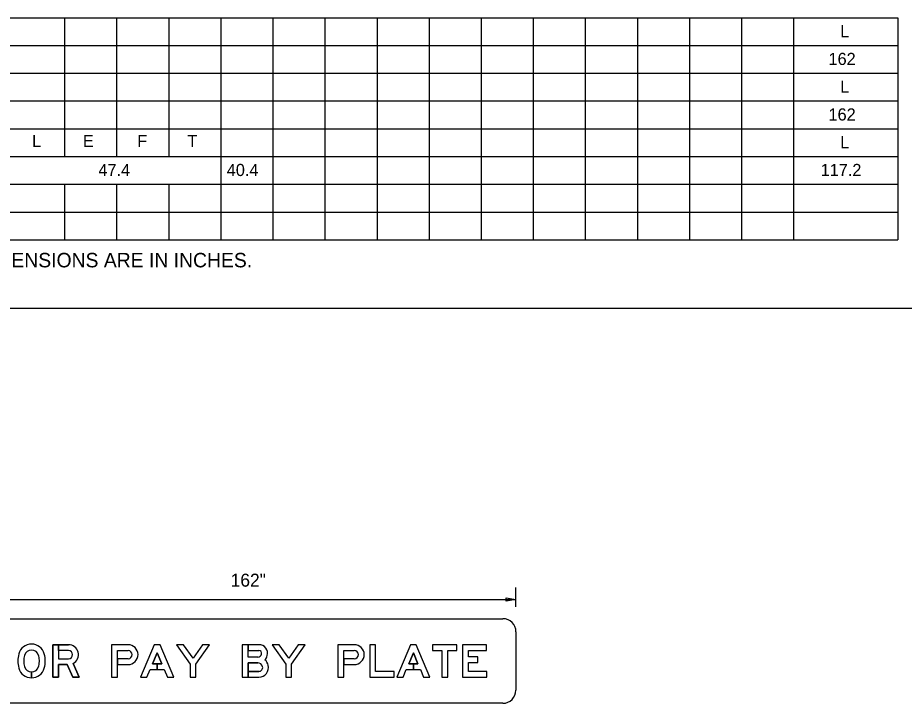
# Model space of a CAD drawing. Extents: x 10268312 to 10268706, y 2142548 to 2142786.
# Drawn here: x 10268343.3 to 10268394.4, y 2142617.5 to 2142657 of the extents above; entities that cross this region are included whole.
import ezdxf

# ---------------------------------------------------------------- set-up
doc = ezdxf.new("R2010")
doc.units = 0
for name, color, linetype in [('GSBWFill', 7, 'Continuous'), ('GSDims', 7, 'Continuous'), ('SheetBorder_dp', 7, 'Continuous'), ('SignPanel', 7, 'Continuous'), ('SumBoxLines_dp', 7, 'Continuous'), ('SumBoxLinesMin_dp', 7, 'Continuous'), ('TextLabel', 7, 'Continuous'), ('TextNotes', 7, 'Continuous')]:
    doc.layers.add(name, color=color, linetype=linetype)

msp = doc.modelspace()

# ---------------------------------------------------------------- linework, layer by layer
at = {"layer": 'GSBWFill'}
for p, q in [((10268342.368, 2142622.39), (10268371.236, 2142622.39)), ((10268371.986, 2142621.64), (10268371.986, 2142618.265)), ((10268371.236, 2142617.515), (10268342.368, 2142617.515))]:
    msp.add_line(p, q, dxfattribs=at)
for centre, start, end in [((10268371.236, 2142621.64), 0, 90), ((10268371.229, 2142618.265), 270, 0)]:
    msp.add_arc(centre, 0.75, start, end, dxfattribs=at)
at = {"layer": 'GSDims'}
for p, q in [((10268371.986, 2142623.07), (10268371.986, 2142624.195)), ((10268341.618, 2142623.492), (10268371.986, 2142623.492))]:
    msp.add_line(p, q, dxfattribs=at)
msp.add_lwpolyline([(10268371.986, 2142623.492), (10268371.424, 2142623.398), (10268371.424, 2142623.586)], close=True, dxfattribs=at)
at = {"layer": 'SheetBorder_dp'}
msp.add_line((10268317.73, 2142640.282), (10268471.73, 2142640.282), dxfattribs=at)
at = {"layer": 'SignPanel'}
for p, q in [((10268349.03, 2142620.552), (10268349.64, 2142620.552)), ((10268349.03, 2142620.552), (10268349.64, 2142620.552)), ((10268349.03, 2142620.552), (10268349.64, 2142620.552)), ((10268362.062, 2142620.552), (10268362.671, 2142620.552)), ((10268362.062, 2142620.552), (10268362.671, 2142620.552)), ((10268362.062, 2142620.552), (10268362.671, 2142620.552)), ((10268344.08, 2142618.982), (10268344.08, 2142619.319)), ((10268344.08, 2142619.319), (10268344.08, 2142618.982)), ((10268344.08, 2142618.982), (10268344.08, 2142619.319)), ((10268344.08, 2142619.319), (10268344.08, 2142618.982)), ((10268349.03, 2142619.746), (10268349.64, 2142619.746)), ((10268362.062, 2142619.746), (10268362.671, 2142619.746)), ((10268356.212, 2142619.015), (10268357.177, 2142619.015))]:
    msp.add_line(p, q, dxfattribs=at)
for points in [[(10268346.206, 2142620.89), (10268345.299, 2142620.89), (10268345.299, 2142619.015), (10268345.637, 2142619.015), (10268345.637, 2142619.746), (10268346.133, 2142619.746), (10268346.45, 2142619.015), (10268346.818, 2142619.015), (10268346.473, 2142619.812)], [(10268346.473, 2142619.812), (10268346.818, 2142619.015), (10268346.45, 2142619.015), (10268346.133, 2142619.746), (10268345.637, 2142619.746), (10268345.637, 2142619.015), (10268345.299, 2142619.015), (10268345.299, 2142620.89), (10268345.637, 2142620.89), (10268345.637, 2142620.083), (10268346.206, 2142620.083)], [(10268346.473, 2142619.812), (10268346.818, 2142619.015), (10268346.45, 2142619.015), (10268346.133, 2142619.746), (10268345.637, 2142619.746), (10268345.637, 2142619.015), (10268345.299, 2142619.015), (10268345.299, 2142620.89), (10268345.637, 2142620.89), (10268345.637, 2142620.083), (10268346.206, 2142620.083)], [(10268345.637, 2142620.552), (10268345.637, 2142620.89), (10268346.206, 2142620.89)], [(10268345.637, 2142620.552), (10268345.637, 2142620.89), (10268346.206, 2142620.89)], [(10268349.64, 2142620.89), (10268348.693, 2142620.89), (10268348.693, 2142619.015), (10268349.03, 2142619.015), (10268349.03, 2142619.746)], [(10268349.64, 2142620.89), (10268348.693, 2142620.89), (10268348.693, 2142619.015), (10268349.03, 2142619.015), (10268349.03, 2142620.552)], [(10268349.64, 2142620.89), (10268348.693, 2142620.89), (10268348.693, 2142619.015), (10268349.03, 2142619.015), (10268349.03, 2142620.552)], [(10268357.177, 2142620.89), (10268356.212, 2142620.89), (10268356.212, 2142619.015)], [(10268357.105, 2142620.177), (10268356.549, 2142620.177), (10268356.549, 2142620.89), (10268356.212, 2142620.89), (10268356.212, 2142619.015), (10268356.549, 2142619.015)], [(10268357.105, 2142620.177), (10268356.549, 2142620.177), (10268356.549, 2142620.89), (10268356.212, 2142620.89), (10268356.212, 2142619.015), (10268356.549, 2142619.015)], [(10268357.177, 2142620.89), (10268356.549, 2142620.89), (10268356.549, 2142620.552), (10268357.177, 2142620.552)], [(10268357.177, 2142620.89), (10268356.549, 2142620.89), (10268356.549, 2142620.552), (10268357.177, 2142620.552)], [(10268362.671, 2142620.89), (10268361.724, 2142620.89), (10268361.724, 2142619.015), (10268362.062, 2142619.015), (10268362.062, 2142619.746)], [(10268362.671, 2142620.89), (10268361.724, 2142620.89), (10268361.724, 2142619.015), (10268362.062, 2142619.015), (10268362.062, 2142620.552)], [(10268362.671, 2142620.89), (10268361.724, 2142620.89), (10268361.724, 2142619.015), (10268362.062, 2142619.015), (10268362.062, 2142620.552)], [(10268346.206, 2142620.552), (10268345.637, 2142620.552), (10268345.637, 2142620.083), (10268346.206, 2142620.083)], [(10268346.206, 2142620.552), (10268345.637, 2142620.552)], [(10268346.206, 2142620.552), (10268345.637, 2142620.552)], [(10268349.64, 2142620.083), (10268349.03, 2142620.083), (10268349.03, 2142620.552)], [(10268357.105, 2142620.177), (10268356.549, 2142620.177), (10268356.549, 2142620.552), (10268357.177, 2142620.552)], [(10268362.671, 2142620.083), (10268362.062, 2142620.083), (10268362.062, 2142620.552)], [(10268349.64, 2142620.083), (10268349.03, 2142620.083), (10268349.03, 2142619.746), (10268349.64, 2142619.746)], [(10268349.64, 2142620.083), (10268349.03, 2142620.083), (10268349.03, 2142619.746), (10268349.64, 2142619.746)], [(10268357.105, 2142619.84), (10268356.549, 2142619.84), (10268356.549, 2142619.352), (10268357.177, 2142619.352)], [(10268356.549, 2142619.015), (10268356.549, 2142619.84), (10268357.105, 2142619.84)], [(10268356.549, 2142619.015), (10268356.549, 2142619.84), (10268357.105, 2142619.84)], [(10268362.671, 2142620.083), (10268362.062, 2142620.083), (10268362.062, 2142619.746), (10268362.671, 2142619.746)], [(10268362.671, 2142620.083), (10268362.062, 2142620.083), (10268362.062, 2142619.746), (10268362.671, 2142619.746)], [(10268357.177, 2142619.352), (10268356.549, 2142619.352), (10268356.549, 2142619.015), (10268357.177, 2142619.015)], [(10268357.177, 2142619.352), (10268356.549, 2142619.352), (10268356.549, 2142619.015), (10268357.177, 2142619.015)]]:
    msp.add_lwpolyline(points, dxfattribs=at)
for points in [[(10268350.913, 2142619.455), (10268351.723, 2142619.455), (10268351.908, 2142619.015), (10268352.274, 2142619.015), (10268351.487, 2142620.89), (10268351.149, 2142620.89), (10268350.362, 2142619.015), (10268350.728, 2142619.015)], [(10268351.581, 2142619.793), (10268351.318, 2142619.793), (10268351.318, 2142619.455), (10268351.723, 2142619.455), (10268351.908, 2142619.015), (10268352.274, 2142619.015), (10268351.487, 2142620.89), (10268351.149, 2142620.89), (10268350.362, 2142619.015), (10268350.728, 2142619.015), (10268350.913, 2142619.455), (10268351.318, 2142619.455), (10268351.318, 2142619.793), (10268351.054, 2142619.793), (10268351.318, 2142620.42)], [(10268351.581, 2142619.793), (10268351.318, 2142619.793), (10268351.318, 2142619.455), (10268351.723, 2142619.455), (10268351.908, 2142619.015), (10268352.274, 2142619.015), (10268351.487, 2142620.89), (10268351.149, 2142620.89), (10268350.362, 2142619.015), (10268350.728, 2142619.015), (10268350.913, 2142619.455), (10268351.318, 2142619.455), (10268351.318, 2142619.793), (10268351.054, 2142619.793), (10268351.318, 2142620.42)], [(10268353.549, 2142619.774), (10268354.337, 2142620.89), (10268353.923, 2142620.89), (10268353.38, 2142620.12), (10268352.837, 2142620.89), (10268352.424, 2142620.89), (10268353.212, 2142619.774), (10268353.212, 2142619.015), (10268353.549, 2142619.015)], [(10268353.549, 2142619.774), (10268354.337, 2142620.89), (10268353.923, 2142620.89), (10268353.38, 2142620.12), (10268352.837, 2142620.89), (10268352.424, 2142620.89), (10268353.212, 2142619.774), (10268353.212, 2142619.015), (10268353.549, 2142619.015)], [(10268353.549, 2142619.774), (10268354.337, 2142620.89), (10268353.923, 2142620.89), (10268353.38, 2142620.12), (10268352.837, 2142620.89), (10268352.424, 2142620.89), (10268353.212, 2142619.774), (10268353.212, 2142619.015), (10268353.549, 2142619.015)], [(10268359.062, 2142619.774), (10268359.849, 2142620.89), (10268359.436, 2142620.89), (10268358.893, 2142620.12), (10268358.35, 2142620.89), (10268357.937, 2142620.89), (10268358.724, 2142619.774), (10268358.724, 2142619.015), (10268359.062, 2142619.015)], [(10268359.062, 2142619.774), (10268359.849, 2142620.89), (10268359.436, 2142620.89), (10268358.893, 2142620.12), (10268358.35, 2142620.89), (10268357.937, 2142620.89), (10268358.724, 2142619.774), (10268358.724, 2142619.015), (10268359.062, 2142619.015)], [(10268359.062, 2142619.774), (10268359.849, 2142620.89), (10268359.436, 2142620.89), (10268358.893, 2142620.12), (10268358.35, 2142620.89), (10268357.937, 2142620.89), (10268358.724, 2142619.774), (10268358.724, 2142619.015), (10268359.062, 2142619.015)], [(10268364.968, 2142619.015), (10268364.968, 2142619.343), (10268363.899, 2142619.343), (10268363.899, 2142620.89), (10268363.562, 2142620.89), (10268363.562, 2142619.015)], [(10268364.968, 2142619.015), (10268364.968, 2142619.343), (10268363.899, 2142619.343), (10268363.899, 2142620.89), (10268363.562, 2142620.89), (10268363.562, 2142619.015)], [(10268364.968, 2142619.015), (10268364.968, 2142619.343), (10268363.899, 2142619.343), (10268363.899, 2142620.89), (10268363.562, 2142620.89), (10268363.562, 2142619.015)], [(10268365.669, 2142619.455), (10268366.479, 2142619.455), (10268366.664, 2142619.015), (10268367.03, 2142619.015), (10268366.243, 2142620.89), (10268365.905, 2142620.89), (10268365.118, 2142619.015), (10268365.484, 2142619.015)], [(10268366.338, 2142619.793), (10268366.074, 2142619.793), (10268366.074, 2142619.455), (10268366.479, 2142619.455), (10268366.664, 2142619.015), (10268367.03, 2142619.015), (10268366.243, 2142620.89), (10268365.905, 2142620.89), (10268365.118, 2142619.015), (10268365.484, 2142619.015), (10268365.669, 2142619.455), (10268366.074, 2142619.455), (10268366.074, 2142619.793), (10268365.811, 2142619.793), (10268366.074, 2142620.42)], [(10268366.338, 2142619.793), (10268366.074, 2142619.793), (10268366.074, 2142619.455), (10268366.479, 2142619.455), (10268366.664, 2142619.015), (10268367.03, 2142619.015), (10268366.243, 2142620.89), (10268365.905, 2142620.89), (10268365.118, 2142619.015), (10268365.484, 2142619.015), (10268365.669, 2142619.455), (10268366.074, 2142619.455), (10268366.074, 2142619.793), (10268365.811, 2142619.793), (10268366.074, 2142620.42)], [(10268367.18, 2142620.552), (10268367.715, 2142620.552), (10268367.715, 2142619.015), (10268368.052, 2142619.015), (10268368.052, 2142620.552), (10268368.587, 2142620.552), (10268368.587, 2142620.89), (10268367.18, 2142620.89)], [(10268367.18, 2142620.552), (10268367.715, 2142620.552), (10268367.715, 2142619.015), (10268368.052, 2142619.015), (10268368.052, 2142620.552), (10268368.587, 2142620.552), (10268368.587, 2142620.89), (10268367.18, 2142620.89)], [(10268367.18, 2142620.552), (10268367.715, 2142620.552), (10268367.715, 2142619.015), (10268368.052, 2142619.015), (10268368.052, 2142620.552), (10268368.587, 2142620.552), (10268368.587, 2142620.89), (10268367.18, 2142620.89)], [(10268370.312, 2142619.352), (10268369.243, 2142619.352), (10268369.243, 2142619.856), (10268369.796, 2142619.856), (10268369.796, 2142620.194), (10268369.243, 2142620.194), (10268369.243, 2142620.552), (10268370.284, 2142620.552), (10268370.284, 2142620.89), (10268368.905, 2142620.89), (10268368.905, 2142619.015), (10268370.312, 2142619.015)], [(10268370.312, 2142619.352), (10268369.243, 2142619.352), (10268369.243, 2142619.856), (10268369.796, 2142619.856), (10268369.796, 2142620.194), (10268369.243, 2142620.194), (10268369.243, 2142620.552), (10268370.284, 2142620.552), (10268370.284, 2142620.89), (10268368.905, 2142620.89), (10268368.905, 2142619.015), (10268370.312, 2142619.015)], [(10268370.312, 2142619.352), (10268369.243, 2142619.352), (10268369.243, 2142619.856), (10268369.796, 2142619.856), (10268369.796, 2142620.194), (10268369.243, 2142620.194), (10268369.243, 2142620.552), (10268370.284, 2142620.552), (10268370.284, 2142620.89), (10268368.905, 2142620.89), (10268368.905, 2142619.015), (10268370.312, 2142619.015)], [(10268351.581, 2142619.793), (10268351.318, 2142620.42), (10268351.054, 2142619.793)], [(10268366.338, 2142619.793), (10268366.074, 2142620.42), (10268365.811, 2142619.793)]]:
    msp.add_lwpolyline(points, close=True, dxfattribs=at)
for centre, radius, start, end in [((10268344.08, 2142620.163), 0.76, 14.9618, 165.0382), ((10268344.08, 2142620.163), 0.76, 14.9618, 165.0382), ((10268344.08, 2142620.163), 0.76, 14.9618, 165.0382), ((10268346.206, 2142620.318), 0.572, 297.837, 90), ((10268346.206, 2142620.318), 0.572, 297.837, 90), ((10268346.206, 2142620.318), 0.572, 297.837, 90), ((10268349.64, 2142620.318), 0.572, 270, 90), ((10268349.64, 2142620.318), 0.572, 270, 90), ((10268349.64, 2142620.318), 0.572, 270, 90), ((10268357.177, 2142620.393), 0.497, 345.5225, 90), ((10268357.177, 2142620.393), 0.497, 345.5225, 90), ((10268357.177, 2142620.393), 0.497, 345.5225, 90), ((10268362.671, 2142620.318), 0.572, 270, 90), ((10268362.671, 2142620.318), 0.572, 270, 90), ((10268362.671, 2142620.318), 0.572, 270, 90), ((10268344.868, 2142619.952), 1.575, 165.0382, 194.9618), ((10268344.868, 2142619.952), 1.575, 165.0382, 194.9618), ((10268344.868, 2142619.952), 1.575, 165.0382, 194.9618), ((10268344.08, 2142620.163), 0.422, 14.9618, 165.0382), ((10268344.08, 2142620.163), 0.422, 14.9618, 165.0382), ((10268344.08, 2142620.163), 0.422, 14.9618, 165.0382), ((10268343.293, 2142619.952), 1.575, 345.0382, 14.9618), ((10268343.293, 2142619.952), 1.575, 345.0382, 14.9618), ((10268343.293, 2142619.952), 1.575, 345.0382, 14.9618), ((10268346.206, 2142620.318), 0.234, 270, 90), ((10268346.206, 2142620.318), 0.234, 270, 90), ((10268346.206, 2142620.318), 0.234, 270, 90), ((10268349.64, 2142620.318), 0.234, 270, 90), ((10268349.64, 2142620.318), 0.234, 270, 90), ((10268349.64, 2142620.318), 0.234, 270, 90), ((10268357.105, 2142620.412), 0.234, 270, 345.5225), ((10268357.105, 2142620.412), 0.234, 270, 345.5225), ((10268357.105, 2142620.412), 0.234, 270, 345.5225), ((10268357.177, 2142620.393), 0.159, 345.5225, 90), ((10268357.177, 2142620.393), 0.159, 345.5225, 90), ((10268357.177, 2142620.393), 0.159, 345.5225, 90), ((10268362.671, 2142620.318), 0.234, 270, 90), ((10268362.671, 2142620.318), 0.234, 270, 90), ((10268362.671, 2142620.318), 0.234, 270, 90), ((10268344.868, 2142619.952), 1.238, 165.0382, 194.9618), ((10268344.868, 2142619.952), 1.238, 165.0382, 194.9618), ((10268344.868, 2142619.952), 1.238, 165.0382, 194.9618), ((10268343.293, 2142619.952), 1.238, 345.0382, 14.9618), ((10268343.293, 2142619.952), 1.238, 345.0382, 14.9618), ((10268343.293, 2142619.952), 1.238, 345.0382, 14.9618), ((10268357.105, 2142619.549), 0.291, 14.4775, 90), ((10268357.105, 2142619.549), 0.291, 14.4775, 90), ((10268357.105, 2142619.549), 0.291, 14.4775, 90), ((10268357.105, 2142620.412), 0.572, 316.7114, 345.5225), ((10268357.105, 2142620.412), 0.572, 316.7114, 345.5225), ((10268357.105, 2142620.412), 0.572, 316.7114, 345.5225), ((10268357.105, 2142619.549), 0.628, 14.4775, 48.4921), ((10268357.105, 2142619.549), 0.628, 14.4775, 48.4921), ((10268357.105, 2142619.549), 0.628, 14.4775, 48.4921), ((10268344.08, 2142619.742), 0.76, 194.9618, 345.0382), ((10268344.08, 2142619.742), 0.76, 194.9618, 270), ((10268344.08, 2142619.742), 0.76, 194.9618, 270), ((10268344.08, 2142619.742), 0.422, 194.9618, 345.0382), ((10268344.08, 2142619.742), 0.422, 194.9618, 270), ((10268344.08, 2142619.742), 0.422, 194.9618, 270), ((10268344.08, 2142619.742), 0.422, 270.0127, 345.0382), ((10268344.08, 2142619.742), 0.422, 270.0127, 345.0382), ((10268344.08, 2142619.742), 0.76, 270.0071, 345.0382), ((10268344.08, 2142619.742), 0.76, 270.0071, 345.0382), ((10268357.177, 2142619.568), 0.553, 270, 14.4775), ((10268357.177, 2142619.568), 0.553, 270, 14.4775), ((10268357.177, 2142619.568), 0.553, 270, 14.4775), ((10268357.177, 2142619.568), 0.216, 270, 14.4775), ((10268357.177, 2142619.568), 0.216, 270, 14.4775), ((10268357.177, 2142619.568), 0.216, 270, 14.4775)]:
    msp.add_arc(centre, radius, start, end, dxfattribs=at)
at = {"layer": 'SumBoxLines_dp'}
for p, q in [((10268318.48, 2142657.032), (10268393.98, 2142657.032)), ((10268345.98, 2142657.032), (10268345.98, 2142653.832)), ((10268348.98, 2142657.032), (10268348.98, 2142653.832)), ((10268351.98, 2142657.032), (10268351.98, 2142653.832)), ((10268354.98, 2142657.032), (10268354.98, 2142653.832)), ((10268357.98, 2142657.032), (10268357.98, 2142655.432)), ((10268360.98, 2142657.032), (10268360.98, 2142655.432)), ((10268363.98, 2142657.032), (10268363.98, 2142653.832)), ((10268366.98, 2142657.032), (10268366.98, 2142653.832)), ((10268369.98, 2142657.032), (10268369.98, 2142655.432)), ((10268372.98, 2142657.032), (10268372.98, 2142655.432)), ((10268375.98, 2142657.032), (10268375.98, 2142655.432)), ((10268378.98, 2142657.032), (10268378.98, 2142655.432)), ((10268381.98, 2142657.032), (10268381.98, 2142655.432)), ((10268384.98, 2142657.032), (10268384.98, 2142655.432)), ((10268387.98, 2142657.032), (10268387.98, 2142655.432)), ((10268393.98, 2142657.032), (10268393.98, 2142644.232)), ((10268357.98, 2142655.432), (10268357.98, 2142649.032)), ((10268360.98, 2142655.432), (10268360.98, 2142647.432)), ((10268363.98, 2142655.432), (10268363.98, 2142647.432)), ((10268366.98, 2142655.432), (10268366.98, 2142649.032)), ((10268369.98, 2142655.432), (10268369.98, 2142649.032)), ((10268372.98, 2142655.432), (10268372.98, 2142644.232)), ((10268375.98, 2142655.432), (10268375.98, 2142644.232)), ((10268378.98, 2142655.432), (10268378.98, 2142649.032)), ((10268381.98, 2142655.432), (10268381.98, 2142649.032)), ((10268384.98, 2142655.432), (10268384.98, 2142649.032)), ((10268387.98, 2142655.432), (10268387.98, 2142644.232)), ((10268318.48, 2142653.832), (10268393.98, 2142653.832)), ((10268345.98, 2142653.832), (10268345.98, 2142650.632)), ((10268348.98, 2142653.832), (10268348.98, 2142650.632)), ((10268351.98, 2142653.832), (10268351.98, 2142650.632)), ((10268354.98, 2142653.832), (10268354.98, 2142649.032)), ((10268318.48, 2142650.632), (10268393.98, 2142650.632)), ((10268345.98, 2142650.632), (10268345.98, 2142649.032)), ((10268348.98, 2142650.632), (10268348.98, 2142649.032)), ((10268351.98, 2142650.632), (10268351.98, 2142649.032)), ((10268354.98, 2142649.032), (10268354.98, 2142644.232)), ((10268357.98, 2142649.032), (10268357.98, 2142644.232)), ((10268366.98, 2142649.032), (10268366.98, 2142644.232)), ((10268369.98, 2142649.032), (10268369.98, 2142644.232)), ((10268378.98, 2142649.032), (10268378.98, 2142644.232)), ((10268381.98, 2142649.032), (10268381.98, 2142644.232)), ((10268384.98, 2142649.032), (10268384.98, 2142644.232)), ((10268318.48, 2142647.432), (10268393.98, 2142647.432)), ((10268345.98, 2142647.432), (10268345.98, 2142644.232)), ((10268348.98, 2142647.432), (10268348.98, 2142644.232)), ((10268351.98, 2142647.432), (10268351.98, 2142644.232)), ((10268360.98, 2142647.432), (10268360.98, 2142644.232)), ((10268363.98, 2142647.432), (10268363.98, 2142644.232)), ((10268318.48, 2142644.232), (10268393.98, 2142644.232))]:
    msp.add_line(p, q, dxfattribs=at)
at = {"layer": 'SumBoxLinesMin_dp'}
for p, q in [((10268318.48, 2142655.432), (10268393.98, 2142655.432)), ((10268318.48, 2142652.232), (10268393.98, 2142652.232)), ((10268318.48, 2142649.032), (10268393.98, 2142649.032)), ((10268318.48, 2142645.832), (10268393.98, 2142645.832))]:
    msp.add_line(p, q, dxfattribs=at)

# ---------------------------------------------------------------- texts
at = {"layer": 'GSDims'}
msp.add_text('162"', height=0.75, dxfattribs=at).set_placement((10268355.548, 2142624.236))
at = {"layer": 'TextLabel'}
for s, p in [('L', (10268390.668, 2142655.907)), ('162', (10268389.993, 2142654.307)), ('L', (10268390.668, 2142652.707)), ('162', (10268389.993, 2142651.107)), ('L', (10268344.112, 2142649.576)), ('E', (10268347.033, 2142649.576)), ('F', (10268350.168, 2142649.576)), ('T', (10268353.056, 2142649.576)), ('L', (10268390.668, 2142649.507)), ('47.4', (10268347.934, 2142647.907)), ('40.4', (10268355.326, 2142647.907)), ('117.2', (10268389.541, 2142647.907))]:
    msp.add_text(s, height=0.7, dxfattribs=at).set_placement(p)
at = {"layer": 'TextNotes'}
msp.add_text('NOTE:  WIDTH - HORIZONTAL SPACING DIMENSIONS ARE IN INCHES.', height=0.83333, dxfattribs=at).set_placement((10268319.392, 2142642.643))

doc.saveas('drawing.dxf')
